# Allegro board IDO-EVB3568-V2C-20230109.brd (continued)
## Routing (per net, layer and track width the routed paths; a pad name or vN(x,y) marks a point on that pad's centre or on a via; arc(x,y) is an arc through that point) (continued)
MIPI_CSI_CLK0P: length 6
  TOP w0.102: J19.18 57.52,9.57 57.65,9.69 57.65,10.02 57.86,10.24 57.86,11 57.73,11.13 D99.9 D99.2 57.73,12.84 57.85,12.96 57.85,13.1 57.75,13.21 57.75,13.71 57.43,14.02 57.43,14.02 R147.2
MIPI_CSI_CLK1N: length 6.5
  TOP w0.102: J20.17 38.96,9.35 38.83,9.48 38.83,10.89 38.24,11.48 37.11,11.48 37.01,11.58 37.01,11.83 D105.1 37.06,12.6 37.06,13.04 R158.2
MIPI_CSI_CLK1P: length 6.5
  TOP w0.102: J20.18 38.46,9.35 38.58,9.47 38.58,10.78 38.13,11.23 37,11.23 36.75,11.48 36.75,11.83 D106.1 36.7,12.6 36.7,13.06 36.42,13.34 R157.2
MIPI_CSI_D0N: length 6
  TOP w0.102: R139.8 61.46,14.19 61.32,14.05 61.32,13.4 61.02,13.1 61.02,12.76 61.15,12.64 D98.1 D98.10 61.15,10.98 61.02,10.86 61.02,9.99 60.9,9.87 60.9,9.69 61.02,9.57 J19.11
MIPI_CSI_D0P: length 6
  TOP w0.102: R139.7 60.91,14.18 61.06,14.02 61.06,13.5 60.77,13.21 60.77,12.76 60.65,12.64 D98.2 D98.9 60.65,11.01 60.77,10.88 60.77,10.1 60.65,9.97 60.65,9.69 60.52,9.57 J19.12
MIPI_CSI_D1N: length 6.1
  TOP w0.102: R139.6 60.3,14.23 60.3,13.93 59.52,13.15 59.52,12.96 59.65,12.84 D98.4 D98.7 59.65,11.01 59.52,10.88 59.52,10.5 59.41,10.39 59.41,9.69 59.52,9.57 J19.14
MIPI_CSI_D1P: length 6.1
  TOP w0.102: J19.15 59.02,9.57 59.16,9.7 59.16,10.49 59.27,10.61 59.27,10.86 59.15,10.98 D98.6 D98.5 59.15,12.84 59.27,12.96 59.27,13.26 59.99,13.98 59.99,14.19 R139.5
MIPI_CSI_D2N: length 6.3
  TOP w0.102: J19.20 56.52,9.41 56.4,9.54 56.4,10.32 56.6,10.52 56.6,10.88 56.73,11.01 D99.7 D99.4 56.73,12.84 56.6,12.96 56.6,13.21 56.35,13.46 55.96,13.46 55.65,13.77 55.65,13.92 55.79,14.06 R140.8
MIPI_CSI_D2N_: length 30.7
  TOP w0.102: v2(52.68,11.81) 52.68,12.2 52.52,12.36 52.52,12.67 52.27,12.92 51.68,12.92 50.95,12.2 50.65,12.2 50.5,12.35 v2(50.5,12.39) ; v1(41.56,12.39) 41.34,12.17 41.34,12.06 41.46,11.94 D104.1 D104.10 41.46,10.47 41.34,10.35 41.34,10.25 41.83,9.76 41.83,9.5 41.96,9.38 J20.11
  BOTTOM w0.102: R141.5 55.74,13.89 55.84,13.79 56.08,13.79 57.52,13.79 58.58,13.79 58.98,13.39 58.98,12.91 58.98,12.7 58.55,12.27 56.23,12.27 55.93,12.57 55.68,12.57 55.37,12.27 54.91,12.27 54.61,12.57 54.36,12.57 54.05,12.27 52.63,12.27 52.5,12.14 52.5,11.91 52.61,11.81 v2(52.68,11.81) ; v1(41.56,12.39) 41.33,12.15 41.33,11.28 41.63,10.97 43.56,10.97 44.47,11.89 49.24,11.89 49.6,12.24 50.32,12.24 50.46,12.39 v2(50.5,12.39)
MIPI_CSI_D2P: length 6.3
  TOP w0.102: J19.21 56.02,9.42 56.15,9.54 56.15,10.43 56.35,10.63 56.35,10.86 56.23,10.98 D99.6 D99.5 56.23,12.84 56.35,12.96 56.35,13.1 56.25,13.21 55.85,13.21 55.39,13.67 55.39,13.85 55.24,14 R140.7
MIPI_CSI_D2P_: length 30.8
  TOP w0.102: v2(50.5,11.81) 50.63,11.94 51.06,11.94 51.78,12.67 52.16,12.67 52.26,12.57 52.26,12.36 52.1,12.2 v2(52.1,11.81) ; v1(40.87,12.39) 41.09,12.17 41.09,12.07 40.96,11.94 D104.2 D104.9 40.96,10.5 41.09,10.38 41.09,10.15 41.58,9.65 41.58,9.45 41.46,9.33 J20.12
  BOTTOM w0.102: v2(52.1,11.81) 52.25,11.95 52.25,12.25 52.52,12.52 53.95,12.52 54.25,12.83 54.71,12.83 55.02,12.52 55.27,12.52 55.57,12.83 56.03,12.83 56.34,12.52 58.44,12.52 58.72,12.81 58.72,13.28 58.47,13.53 57.41,13.53 57.41,13.53 57.04,13.53 57.04,13.53 55.98,13.53 55.66,13.53 55.19,14 R141.6 ; v1(40.87,12.39) 41.07,12.18 41.07,11.17 41.53,10.72 43.66,10.72 44.58,11.63 49.35,11.63 49.7,11.99 50.27,11.99 50.44,11.81 v2(50.5,11.81)
MIPI_CSI_D3N: length 6.1
  TOP w0.102: J19.23 55.02,9.39 54.9,9.51 54.9,10 54.56,10.34 54.56,10.9 D100.1 55.06,11.41 54.56,11.91 54.56,13.72 54.74,13.9 R140.6
MIPI_CSI_D3N_: length 25.4
  TOP w0.102: v1(40.06,12.43) 39.81,12.18 39.81,12.03 39.96,11.88 D104.4 D104.7 39.96,10.5 39.84,10.38 39.84,10.25 40.33,9.76 40.33,9.48 40.46,9.35 J20.14
  BOTTOM w0.102: v1(40.06,12.43) 40.06,12.49 39.86,12.69 39.86,13.17 40.01,13.31 40.18,13.31 40.58,12.92 41.94,12.92 42.14,12.72 42.14,11.76 42.54,11.35 43.31,11.35 43.64,11.68 43.64,12.67 43.87,12.9 44.21,12.9 44.31,12.8 44.31,12.49 44.56,12.24 44.98,12.24 45.23,12.49 45.23,12.8 45.33,12.9 45.53,12.9 45.63,12.8 45.63,12.49 45.88,12.24 46.3,12.24 46.55,12.49 46.55,12.8 46.65,12.9 50.8,12.9 51.16,12.55 51.84,12.55 52.2,12.9 53.87,12.9 54.58,13.62 54.58,13.92 54.69,14.02 R141.7
MIPI_CSI_D3P: length 6.1
  TOP w0.102: J19.24 54.52,9.44 54.65,9.56 54.65,9.89 54.31,10.24 54.31,10.9 D101.1 53.8,11.41 54.31,11.91 54.31,13.79 54.19,13.91 R140.5
MIPI_CSI_D3P_: length 25.4
  TOP w0.102: v1(39.31,12.43) 39.55,12.19 39.55,12.02 39.46,11.93 D104.5 D104.6 39.46,10.47 39.59,10.35 39.59,10.15 40.08,9.65 40.08,9.47 39.96,9.35 J20.15
  BOTTOM w0.102: R141.8 54.14,14.11 54.33,13.92 54.33,13.73 53.76,13.16 52.09,13.16 51.74,12.8 51.26,12.8 50.91,13.16 46.54,13.16 46.29,12.91 46.29,12.6 46.19,12.5 45.99,12.5 45.89,12.6 45.89,12.91 45.64,13.16 45.22,13.16 44.97,12.91 44.97,12.6 44.87,12.5 44.67,12.5 44.57,12.6 44.57,12.91 44.32,13.16 43.76,13.16 43.38,12.78 43.38,11.79 43.21,11.61 42.65,11.61 42.39,11.86 42.39,12.83 42.05,13.17 40.68,13.17 40.29,13.57 39.91,13.57 39.61,13.27 39.61,12.65 39.39,12.43 v1(39.31,12.43)
MIPI_CSI_RX_CLK0N: length 102.5
  TOP w0.102: v1(91.43,33.36) 91.19,33.6 90.67,33.6 90.42,33.85 90.42,34.72 90.88,35.18 90.88,36.88 91.64,37.65 91.64,54.5 89.15,56.99 89.15,58.16 88.03,59.29 86.11,59.29 84.89,58.06 62.79,58.06 60.8,60.06 60.8,60.28 60.67,60.4 J2.103 ; v1(58.31,16.19) 58.31,16.18 58.05,15.92 58.05,15.53 R148.1
  BOTTOM w0.102: v1(58.31,16.19) 58.23,16.19 58.06,16.36 58.06,19.35 58.96,20.24 70.39,20.24 80.29,30.15 81.18,30.15 82.42,31.39 85.69,31.39 87.15,32.85 88.32,32.85 88.95,33.48 89.51,33.48 89.61,33.58 91.21,33.58 v1(91.43,33.36)
MIPI_CSI_RX_CLK0P: length 102.5
  TOP w0.102: v1(91.43,34.05) 91.24,33.86 90.78,33.86 90.68,33.96 90.68,34.62 91.14,35.07 91.14,36.78 91.9,37.54 91.9,54.61 89.41,57.1 89.41,58.27 88.13,59.54 86.01,59.54 84.78,58.32 62.89,58.32 61.05,60.16 61.05,60.28 61.17,60.4 J2.101 ; R147.1 57.79,15.62 57.79,15.92 v1(57.53,16.18)
  BOTTOM w0.102: v1(57.53,16.18) 57.63,16.18 57.81,16.36 57.81,19.46 58.85,20.5 70.28,20.5 80.19,30.4 81.08,30.4 82.32,31.65 85.59,31.65 87.04,33.1 88.21,33.1 88.85,33.73 89.41,33.73 89.51,33.83 91.21,33.83 v1(91.43,34.05)
MIPI_CSI_RX_CLK1N: length 126.1
  TOP w0.102: v2(39.57,15.65) 39.41,15.8 37.9,15.8 37.01,14.91 37.01,14.6 R158.1 ; v2(92.43,34.54) 92.43,34.57 92.28,34.72 92.02,34.72 91.73,35.01 91.73,35.78 92.41,36.45 92.41,54.83 89.84,57.4 89.84,58.5 88.37,59.97 85.73,59.97 84.56,58.8 63.12,58.8 61.8,60.12 61.8,60.55 61.67,60.68 J2.99
  BOTTOM w0.102: v2(39.57,15.65) 39.74,15.81 43.61,15.81 44.26,15.16 51.39,15.16 51.88,15.64 51.88,17.06 52.29,17.47 52.29,18.02 52.56,18.29 53.09,18.29 53.34,18.54 53.34,19.52 56.62,22.8 69.8,22.8 78.24,31.23 78.24,32.01 78.7,32.47 80.24,32.47 81.23,33.46 84.96,33.46 88.14,36.64 90.15,36.64 91.14,35.66 91.14,35.03 91.46,34.71 91.87,34.71 92.29,34.71 92.43,34.57 v2(92.43,34.54)
MIPI_CSI_RX_CLK1P: length 126.1
  TOP w0.102: v2(92.43,35.13) 92.43,35.1 92.3,34.98 92.13,34.98 91.99,35.12 91.99,35.67 92.66,36.35 92.66,54.94 90.09,57.51 90.09,58.6 88.47,60.22 85.62,60.22 84.45,59.06 63.22,59.06 62.05,60.23 62.05,60.56 62.17,60.68 J2.97 ; R157.1 36.75,14.57 36.75,15.02 37.79,16.05 39.44,16.05 v2(39.6,16.23)
  BOTTOM w0.102: v2(92.43,35.13) 92.27,34.96 91.87,34.96 91.56,34.96 91.39,35.14 91.39,35.76 90.26,36.89 88.03,36.89 84.86,33.72 81.13,33.72 80.14,32.73 78.59,32.73 77.98,32.12 77.98,31.34 69.7,23.05 56.51,23.05 53.09,19.62 53.09,18.64 52.98,18.54 52.45,18.54 52.03,18.12 52.03,17.57 51.63,17.17 51.63,15.75 51.29,15.41 44.37,15.41 43.72,16.07 39.76,16.07 v2(39.6,16.23)
MIPI_CSI_RX_D0N: length 100.3
  TOP w0.102: J2.119 56.67,60.4 56.8,60.28 56.8,59.66 61.39,55.07 85.06,55.07 85.75,54.38 87.27,54.38 88.6,53.06 88.6,42.62 88.34,42.37 86.31,42.37 86.06,42.12 86.06,41.47 86.31,41.22 88.37,41.22 88.47,41.12 88.47,40.69 88.37,40.59 86.08,40.59 85.8,40.31 85.8,38.3 86.77,37.34 86.77,34.44 83.85,31.52 83.85,29.29 v1(83.64,29.08) ; R139.1 61.46,15.43 61.29,15.6 61.29,15.77 61.62,16.1 61.62,17.01 v1(61.95,17.35)
  BOTTOM w0.102: v1(61.95,17.35) 61.63,17.67 61.63,17.79 62.34,18.49 62.56,18.49 62.69,18.36 62.69,18.03 62.82,17.9 63.06,17.9 63.2,18.03 63.2,18.36 63.32,18.49 70.84,18.49 81.03,28.68 81.87,28.68 82.73,29.54 83.74,29.54 83.85,29.44 83.85,29.29 v1(83.64,29.08)
MIPI_CSI_RX_D0P: length 100.3
  TOP w0.102: J2.117 57.17,60.4 57.05,60.28 57.05,59.76 61.49,55.32 85.17,55.32 85.85,54.64 87.38,54.64 88.85,53.16 88.85,42.52 88.45,42.11 86.41,42.11 86.31,42.01 86.31,41.58 86.41,41.48 88.47,41.48 88.72,41.23 88.72,40.59 88.47,40.34 86.18,40.34 86.06,40.21 86.06,38.41 87.02,37.44 87.02,34.34 84.1,31.42 84.1,29.31 v1(84.33,29.08) ; R139.2 60.91,15.52 61.04,15.65 61.04,15.88 61.36,16.2 61.36,17.05 v1(61.06,17.35)
  BOTTOM w0.102: v1(84.33,29.08) 84.1,29.31 84.1,29.54 83.85,29.79 82.63,29.79 81.76,28.93 80.92,28.93 70.74,18.75 62.23,18.75 61.38,17.89 61.38,17.67 v1(61.06,17.35)
MIPI_CSI_RX_D1N: length 100.4
  TOP w0.102: J2.115 57.67,60.4 57.8,60.28 57.8,59.73 61.69,55.83 85.44,55.83 86.15,55.12 87.66,55.12 89.36,53.42 89.36,40.08 89.1,39.83 86.94,39.83 86.69,39.57 86.69,38.94 86.94,38.68 88.72,38.68 88.85,38.56 88.85,38.28 88.62,38.05 87.85,38.05 87.5,37.7 87.5,34.01 84.81,31.32 84.81,30.21 v1(84.57,29.98) ; v1(60.43,18.14) 60.21,18.35 60.04,18.35 59.83,18.14 59.83,17.11 60.12,16.81 60.6,16.81 60.68,16.74 60.68,16.43 60.6,16.36 60.38,16.36 60.26,16.24 60.26,15.91 60.41,15.76 R139.3
  BOTTOM w0.102: v1(84.57,29.98) 84.78,30.18 84.78,30.28 84.63,30.43 82.52,30.43 81.53,29.44 80.72,29.44 71.05,19.76 62.56,19.76 61.14,18.34 60.63,18.34 v1(60.43,18.14)
MIPI_CSI_RX_D1P: length 100.5
  TOP w0.102: J2.113 58.17,60.4 58.05,60.28 58.05,59.83 61.8,56.08 85.55,56.08 86.26,55.37 87.76,55.37 89.61,53.52 89.61,39.98 89.21,39.57 87.05,39.57 86.94,39.47 86.94,39.04 87.05,38.94 88.83,38.94 89.1,38.66 89.1,38.17 88.73,37.8 87.96,37.8 87.76,37.59 87.76,33.91 85.06,31.22 85.06,30.21 v1(85.28,29.99) ; R139.4 59.86,15.76 60,15.91 60,16.04 59.58,16.47 59.58,18.25 59.93,18.61 60.21,18.61 v1(60.43,18.82)
  BOTTOM w0.102: v1(85.28,29.99) 85.04,30.24 85.04,30.38 84.73,30.68 82.42,30.68 81.43,29.69 80.62,29.69 70.94,20.02 62.45,20.02 61.03,18.59 60.66,18.59 v1(60.43,18.82)
MIPI_CSI_RX_D2N: length 101.4
  TOP w0.102: v1(88.9,34.22) 88.68,34.45 88.49,34.45 88.24,34.7 88.24,36.6 90.12,38.48 90.12,53.8 88.06,55.85 86.56,55.85 85.85,56.57 62.08,56.57 58.8,59.85 58.8,60.28 58.67,60.4 J2.111 ; R140.1 55.78,15.17 55.78,15.64 56.06,15.92 56.06,16.13 v1(56.14,16.21)
  BOTTOM w0.102: R141.4 55.6,15.32 55.6,15.67 v1(56.14,16.21) 56.14,16.29 55.93,16.49 55.93,18.48 56.16,18.71 56.16,19.73 57.71,21.29 70.41,21.29 80.06,30.94 80.88,30.94 81.89,31.95 85.57,31.95 88.06,34.44 88.68,34.44 v1(88.9,34.22)
MIPI_CSI_RX_D2P: length 101.4
  TOP w0.102: R140.2 55.32,15.24 55.32,15.54 55.63,15.86 55.63,16.04 55.48,16.2 v1(55.46,16.2) ; J2.109 59.17,60.4 59.05,60.28 59.05,59.95 62.18,56.82 85.95,56.82 86.66,56.11 88.17,56.11 90.37,53.9 90.37,38.38 88.49,36.5 88.49,34.8 88.6,34.7 88.69,34.7 v1(88.9,34.92)
  BOTTOM w0.102: R141.3 55.19,15.29 55.35,15.44 55.35,15.77 55.48,15.91 55.48,16.18 v1(55.46,16.2) 55.68,16.41 55.68,17.16 55.6,17.23 55.6,17.69 55.68,17.77 55.68,18.59 55.9,18.81 55.9,19.83 57.61,21.54 70.31,21.54 79.96,31.19 80.77,31.19 81.79,32.21 85.47,32.21 87.96,34.7 88.68,34.7 v1(88.9,34.92)
MIPI_CSI_RX_D3N: length 105.1
  TOP w0.102: R140.3 54.74,15.31 54.61,15.44 54.61,15.65 54.5,15.76 54.5,15.99 54.71,16.2 v1(54.72,16.2) ; J2.107 59.67,60.4 59.8,60.28 59.8,59.99 62.48,57.3 85.24,57.3 86.54,58.6 87.7,58.6 88.47,57.83 88.47,56.57 90.88,54.15 90.88,38.18 89.1,36.4 89.1,35.64 89.35,35.39 89.59,35.39 v1(89.81,35.16)
  BOTTOM w0.102: v1(89.81,35.16) 89.59,35.38 87.94,35.38 85.27,32.72 81.59,32.72 80.57,31.7 79.76,31.7 70.08,22.02 56.95,22.02 54.23,19.31 54.23,18.81 54.41,18.64 54.41,17.5 54.56,17.34 54.56,17.09 54.41,16.94 54.41,16.51 v1(54.72,16.2) 54.72,16.18 54.56,16.02 54.56,15.4 54.69,15.27 R141.2
MIPI_CSI_RX_D3P: length 105.2
  TOP w0.102: J2.105 60.17,60.4 60.05,60.28 60.05,60.1 62.59,57.56 85.14,57.56 86.43,58.85 87.81,58.85 88.72,57.94 88.72,56.67 91.14,54.26 91.14,38.07 89.36,36.29 89.36,35.75 89.46,35.64 89.6,35.64 v1(89.81,35.86) ; R140.4 54.36,15.32 54.36,15.54 53.92,15.97 53.92,16.13 v1(53.87,16.18)
  BOTTOM w0.102: v1(89.81,35.86) 89.59,35.64 87.83,35.64 85.17,32.97 81.48,32.97 80.47,31.95 79.65,31.95 69.98,22.28 57.05,22.28 56.84,22.28 53.98,19.41 53.98,18.71 54.15,18.53 54.15,16.46 v1(53.87,16.18) 54.31,15.75 54.31,15.35 R141.1
MIPI_DSI_TX0_CLKN: length 61.8
  TOP w0.102: v1(28.12,36.55) 27.89,36.32 26.29,36.32 26.11,36.5 26.11,36.89 25.77,37.24 25.38,37.24 24.55,38.06 23.58,38.06 23.46,38.18 D51.2 D51.9 21.98,38.18 21.88,38.08 21.74,38.08 21.47,38.35 21.41,38.35 21.29,38.48 21.29,38.56 21.17,38.68 21.02,38.68 20.9,38.56 20.9,38.43 20.83,38.35 20.61,38.35 v1(20.39,38.58) ; J2.133 53.17,60.59 53.3,60.47 53.3,59.62 52.98,59.31 52.98,58.85 53.3,58.54 53.3,58.3 52.98,57.99 52.98,57.53 53.3,57.22 53.3,56.22 53.16,56.08 53.16,55.8 v2(53.02,55.65)
  BOTTOM w0.102: v1(28.12,36.55) 28.37,36.3 28.93,36.3 29.08,36.14 29.36,36.14 29.54,35.97 29.54,35.81 29.69,35.66 30.3,35.66 30.61,35.36 30.86,35.36 31.16,35.66 31.62,35.66 31.93,35.36 32.18,35.36 32.48,35.66 32.94,35.66 33.25,35.36 33.5,35.36 33.8,35.66 34.16,35.66 34.58,36.08 34.58,37 36.25,38.66 36.25,39.27 35.79,39.73 35.79,40.44 36.25,40.89 36.25,42.67 37.72,44.15 37.72,49.4 40.16,51.84 44.48,51.84 45.44,50.88 46.2,50.88 47.32,51.99 48.97,51.99 49.78,52.81 49.78,53.67 50.26,54.15 52.25,54.15 53.19,55.09 53.19,55.48 v2(53.02,55.65) ; v1(20.39,38.58) 20.19,38.38 19.43,38.38 19.31,38.51 J15.27 18.13,38.51 18.01,38.38 17.72,38.38 R127.1
MIPI_DSI_TX0_CLKP: length 61.8
  TOP w0.102: v1(28.12,35.76) 27.81,36.07 26.19,36.07 25.86,36.4 25.86,36.79 25.66,36.98 25.27,36.98 24.45,37.81 23.61,37.81 23.49,37.68 D51.1 D51.10 22.01,37.68 21.86,37.83 21.63,37.83 21.36,38.1 20.6,38.1 v1(20.39,37.88) ; J2.131 53.67,60.61 53.55,60.48 53.55,59.51 53.24,59.2 53.24,58.96 53.55,58.65 53.55,58.19 53.24,57.88 53.24,57.64 53.55,57.33 53.55,56.11 53.42,55.98 53.42,55.83 v2(53.59,55.65)
  BOTTOM w0.102: v2(53.59,55.65) 53.44,55.5 53.44,54.99 52.35,53.9 50.37,53.9 50.04,53.57 50.04,52.7 49.08,51.74 47.42,51.74 46.3,50.62 45.34,50.62 44.37,51.59 40.26,51.59 37.97,49.3 37.97,44.04 36.5,42.57 36.5,40.79 36.04,40.33 36.04,39.83 36.5,39.37 36.5,38.56 34.84,36.89 34.84,35.98 34.27,35.41 33.91,35.41 33.6,35.1 33.14,35.1 32.84,35.41 32.59,35.41 32.28,35.1 31.82,35.1 31.52,35.41 31.27,35.41 30.96,35.1 30.5,35.1 30.2,35.41 29.46,35.41 28.83,36.04 28.4,36.04 v1(28.12,35.76) ; v1(20.39,37.88) 20.14,38.13 19.46,38.13 19.34,38.01 J15.26 18.1,38.01 18.05,38.06 17.68,38.06 R126.1
MIPI_DSI_TX0_D0N: length 62
  TOP w0.102: J2.141 51.17,60.64 51.3,60.51 51.3,60.31 51.74,59.87 51.74,58.47 49.23,55.96 49.23,54.36 49.13,54.27 48.93,54.27 48.8,54.4 v2(48.79,54.4) ; v1(20.41,41.6) 20.63,41.38 21.74,41.38 21.9,41.22 22.05,41.22 22.2,41.38 D53.1 22.32,41.96 22.93,41.35 23.7,41.35 24.21,40.84 25.91,40.84 26.8,39.95 28.2,39.95 28.64,39.51 v1(28.94,39.51)
  BOTTOM w0.102: R122.1 17.63,41.17 17.78,41.17 18.11,41.51 J15.33 19.35,41.51 19.46,41.4 20.21,41.4 v1(20.41,41.6) ; v1(28.94,39.51) 28.94,39.11 29.06,38.99 29.06,37.9 29.36,37.59 29.82,37.59 30.4,37.01 32.77,37.01 34.06,38.3 34.06,39.47 33.81,39.73 33.81,40.72 34.39,41.3 34.39,43.99 36.42,46.02 36.42,50.24 40.64,54.46 41.53,54.46 41.78,54.21 41.78,53.9 41.89,53.8 42.09,53.8 42.19,53.9 42.19,54.21 42.44,54.46 42.85,54.46 43.11,54.21 43.11,53.9 43.21,53.8 43.41,53.8 43.51,53.9 43.51,54.21 43.76,54.46 44.18,54.46 44.43,54.21 44.43,53.9 44.53,53.8 44.73,53.8 44.83,53.9 44.83,54.21 45.08,54.46 45.5,54.46 45.75,54.21 45.75,53.9 45.85,53.8 46.05,53.8 46.15,53.9 46.15,54.21 46.4,54.46 46.82,54.46 47.07,54.21 47.07,53.9 47.17,53.8 47.37,53.8 47.47,53.9 47.47,54.21 47.72,54.46 48.21,54.46 48.44,54.23 48.62,54.23 v2(48.79,54.4)
MIPI_DSI_TX0_D0P: length 61.8
  TOP w0.102: v2(48.82,53.82) 48.89,53.82 49.08,54.01 49.24,54.01 49.48,54.25 49.48,55.85 51.99,58.37 51.99,59.97 51.55,60.42 51.55,60.52 51.67,60.64 J2.139 ; v1(20.41,40.91) 20.63,41.13 21.64,41.13 D52.1 22.32,40.56 22.85,41.1 23.59,41.1 24.1,40.59 25.8,40.59 26.69,39.7 28.09,39.7 28.47,39.32 v1(28.47,39.01)
  BOTTOM w0.102: v1(28.47,39.01) 28.67,39.01 28.8,38.88 28.8,37.79 29.26,37.34 29.71,37.34 30.3,36.75 32.87,36.75 34.32,38.2 34.32,39.58 34.06,39.83 34.06,40.61 34.65,41.2 34.65,43.89 36.68,45.92 36.68,50.14 40.75,54.2 41.43,54.2 41.53,54.1 41.53,53.79 41.78,53.54 42.19,53.54 42.44,53.79 42.44,54.1 42.55,54.2 42.75,54.2 42.85,54.1 42.85,53.79 43.1,53.54 43.52,53.54 43.77,53.79 43.77,54.1 43.87,54.2 44.07,54.2 44.17,54.1 44.17,53.79 44.42,53.54 44.84,53.54 45.09,53.79 45.09,54.1 45.19,54.2 45.39,54.2 45.49,54.1 45.49,53.79 45.74,53.54 46.16,53.54 46.41,53.79 46.41,54.1 46.51,54.2 46.71,54.2 46.81,54.1 46.81,53.79 47.06,53.54 47.48,53.54 47.73,53.79 47.73,54.1 47.83,54.2 48.11,54.2 48.34,53.98 48.67,53.98 v2(48.82,53.82) ; v1(20.41,40.91) 20.18,41.14 19.43,41.14 19.29,41.01 J15.32 17.99,41.01 17.75,40.76 R122.2
MIPI_DSI_TX0_D1N: length 61.2
  TOP w0.102: v1(20.36,40.15) 20.61,39.9 21.08,39.9 21.41,39.57 21.84,39.57 21.95,39.68 D51.6 D51.5 23.63,39.68 23.76,39.56 25.23,39.56 26.49,38.3 26.75,38.3 26.87,38.43 26.87,38.56 26.99,38.68 27.26,38.68 27.38,38.56 27.38,38.43 27.51,38.3 27.56,38.3 27.84,38.02 v1(28.17,38.02) ; J2.137 52.17,60.53 52.3,60.4 52.3,57.94 52.06,57.7 52.06,57.26 52.3,57.03 52.3,56.77 52.18,56.65 51.7,56.65 51.49,56.87 50.98,56.87 49.78,55.68 49.78,53.42 49.35,52.98 49.1,52.98 v2(48.92,53.16)
  BOTTOM w0.102: v1(20.36,40.15) 20.09,39.88 19.45,39.88 19.33,40.01 J15.30 18.01,40.01 17.89,40.13 17.73,40.13 17.6,40.26 R122.3 ; v1(28.17,38.02) 28.15,37.72 28.81,37.06 29.36,37.06 29.95,36.47 33.78,36.47 33.96,36.66 33.96,37.39 35.03,38.46 35.03,41.76 35.43,42.17 35.43,42.62 35.15,42.9 35.15,43.38 35.43,43.66 35.43,44.02 37.01,45.6 37.01,49.66 40.05,52.7 41.24,52.7 41.34,52.81 41.34,52.94 41.59,53.19 42,53.19 42.25,52.94 42.25,52.81 42.36,52.7 42.56,52.7 42.66,52.81 42.66,52.94 42.91,53.19 43.32,53.19 43.57,52.94 43.57,52.81 43.68,52.7 43.88,52.7 43.98,52.81 43.98,52.94 44.23,53.19 44.65,53.19 44.9,52.94 44.9,52.81 45,52.7 45.2,52.7 45.3,52.81 45.3,52.94 45.55,53.19 45.97,53.19 46.22,52.94 46.22,52.81 46.32,52.7 46.52,52.7 46.62,52.81 46.62,52.94 46.87,53.19 47.29,53.19 47.54,52.94 47.54,52.81 47.64,52.7 48.18,52.7 48.46,52.98 48.75,52.98 48.89,53.13 48.89,53.13 v2(48.92,53.16)
MIPI_DSI_TX0_D1P: length 61.1
  TOP w0.102: v2(48.91,52.58) 49.06,52.73 49.46,52.73 50.04,53.31 50.04,55.57 51.08,56.62 51.38,56.62 51.6,56.4 52.28,56.4 52.55,56.66 52.55,57.13 52.31,57.37 52.31,57.59 52.55,57.83 52.55,60.47 52.67,60.6 J2.135 ; v1(27.64,37.57) 27.64,37.87 27.45,38.05 26.39,38.05 25.13,39.31 23.76,39.31 23.63,39.18 D51.4 D51.7 21.98,39.18 21.84,39.32 21.31,39.32 20.98,39.65 20.58,39.65 v1(20.36,39.43)
  BOTTOM w0.102: v2(48.91,52.58) 48.77,52.73 48.57,52.73 48.29,52.45 47.53,52.45 47.28,52.7 47.28,52.83 47.18,52.93 46.98,52.93 46.88,52.83 46.88,52.7 46.63,52.45 46.21,52.45 45.96,52.7 45.96,52.83 45.86,52.93 45.66,52.93 45.56,52.83 45.56,52.7 45.31,52.45 44.89,52.45 44.64,52.7 44.64,52.83 44.54,52.93 44.34,52.93 44.24,52.83 44.24,52.7 43.98,52.45 43.57,52.45 43.32,52.7 43.32,52.83 43.22,52.93 43.02,52.93 42.91,52.83 42.91,52.7 42.66,52.45 42.25,52.45 42,52.7 42,52.83 41.9,52.93 41.7,52.93 41.59,52.83 41.59,52.7 41.34,52.45 40.16,52.45 37.26,49.56 37.26,45.49 35.69,43.92 35.69,43.56 35.41,43.28 35.41,43 35.69,42.72 35.69,42.06 35.28,41.66 35.28,38.35 34.21,37.29 34.21,36.55 33.88,36.22 29.84,36.22 29.26,36.8 28.7,36.8 27.97,37.54 v1(27.64,37.57) ; v1(20.36,39.43) 20.17,39.63 19.44,39.63 19.31,39.51 J15.29 18.16,39.51 17.79,39.87 17.65,39.87 R122.4
MIPI_DSI_TX0_D2N: length 61.8
  TOP w0.102: v1(20.4,37.11) 20.61,36.89 20.83,36.89 20.9,36.97 20.9,37.16 21.02,37.28 21.17,37.28 21.29,37.16 21.29,37.02 21.41,36.89 21.61,36.89 21.73,37.02 D49.6 D49.5 23.41,37.02 23.53,36.89 24.6,36.89 26.75,34.75 27.84,34.75 v1(28.07,34.98) ; J2.129 54.17,60.61 54.28,60.5 54.28,59.66 54.1,59.48 54.1,58.96 54.28,58.79 54.28,58.34 54.1,58.16 54.1,57.64 54.28,57.47 54.28,55.39 v2(54.06,55.17)
  BOTTOM w0.102: v1(28.07,34.98) 28.3,34.75 34.72,34.75 35.18,35.2 35.18,36.63 36.96,38.41 36.96,42.34 38.4,43.79 38.4,49 40.59,51.18 44.25,51.18 45.19,50.24 46.83,50.24 47.72,51.13 49.02,51.13 51.46,53.57 53.26,53.57 53.37,53.67 53.37,53.92 53.7,54.25 54.1,54.25 54.23,54.38 54.23,55 v2(54.06,55.17) ; v1(20.4,37.11) 20.17,36.88 19.63,36.88 19.5,37.01 J15.24 18.16,37.01 17.99,36.84 17.99,36.84 17.75,36.6 17.61,36.6 R123.1
MIPI_DSI_TX0_D2P: length 61.6
  TOP w0.102: v2(54.74,55.19) 54.53,55.4 54.53,57.57 54.36,57.75 54.36,58.05 54.53,58.23 54.53,58.89 54.36,59.07 54.36,59.37 54.53,59.55 54.53,60.53 54.67,60.67 J2.127 ; v1(20.4,36.43) 20.61,36.64 21.61,36.64 21.73,36.52 D49.7 D49.4 23.46,36.52 23.58,36.64 24.49,36.64 26.64,34.49 27.86,34.49 v1(28.07,34.28)
  BOTTOM w0.102: v1(20.4,36.43) 20.2,36.63 19.63,36.63 19.5,36.51 J15.23 18.12,36.51 17.93,36.32 17.68,36.32 17.57,36.22 R123.2 ; v2(54.74,55.19) 54.48,54.94 54.48,54.28 54.21,54 53.8,54 53.62,53.82 53.62,53.56 53.37,53.31 51.57,53.31 49.13,50.88 47.83,50.88 46.94,49.99 45.08,49.99 44.14,50.93 40.69,50.93 38.66,48.89 38.66,43.68 37.21,42.24 37.21,38.3 35.43,36.53 35.43,35.1 34.83,34.49 28.28,34.49 v1(28.07,34.28)
MIPI_DSI_TX0_D3N: length 63.9
  TOP w0.102: v2(55.24,55.65) 55.5,55.91 55.5,56.13 55.02,56.61 55.02,60.18 55.27,60.43 55.27,60.58 55.17,60.68 J2.125 ; v1(20.37,35.64) 20.6,35.41 20.93,35.41 21.03,35.51 21.03,35.64 21.15,35.75 21.29,35.75 21.41,35.64 21.41,35.53 21.54,35.41 21.79,35.41 21.9,35.52 D49.9 D49.2 23.39,35.52 23.49,35.41 23.91,35.41 26.22,33.1 27.48,33.1 v1(27.73,33.35)
  BOTTOM w0.102: v2(55.24,55.65) 55.47,55.42 55.47,54.39 54.02,52.93 51.82,52.93 48.49,49.61 44.91,49.61 43.87,50.65 41.1,50.65 39.17,48.72 39.17,43.69 37.62,42.14 37.62,38.13 35.79,36.3 35.79,34.09 35.23,33.53 28.47,33.53 28.07,33.13 27.95,33.13 v1(27.73,33.35) ; v1(20.37,35.64) 20.14,35.41 19.48,35.41 19.38,35.51 J15.21 18.18,35.51 18.11,35.43 17.99,35.43 17.81,35.61 17.55,35.61 R123.3
MIPI_DSI_TX0_D3P: length 64
  TOP w0.102: J2.123 55.67,60.65 55.52,60.5 55.52,60.33 55.27,60.07 55.27,56.72 55.75,56.24 55.75,55.88 v2(56.01,55.63) ; v1(20.37,34.95) 20.57,35.15 21.77,35.15 21.9,35.02 D49.10 D49.1 23.43,35.02 23.57,35.15 23.8,35.15 26.11,32.84 27.54,32.84 v1(27.73,32.66)
  BOTTOM w0.102: v2(56.01,55.63) 55.73,55.35 55.73,54.28 54.13,52.68 51.92,52.68 48.59,49.35 44.8,49.35 43.76,50.39 41.2,50.39 39.42,48.61 39.42,43.59 37.87,42.04 37.87,38.02 36.04,36.2 36.04,33.99 35.33,33.27 28.58,33.27 28.18,32.88 27.95,32.88 v1(27.73,32.66) ; R123.4 17.6,35.32 17.74,35.32 18.06,35.01 J15.20 19.38,35.01 19.53,35.15 20.17,35.15 v1(20.37,34.95)
MIPI_DSI_TX0_RST: length 9.6
  TOP w0.127: v1(19.84,42.65) 21.92,42.65 22.56,43.28 C90.2 R417.2 24.13,44.33 24.13,46.51 R121.2
  BOTTOM w0.127: v1(19.84,42.65) 19.48,43.01 J15.36
MIPI_DSI_TX0_RST_GPIO4_C3: length 43.9
  TOP w0.127: v1(51.51,55.19) 52.42,54.28 J2.136 ; v1(31.83,55.7) 31.95,55.58 38.79,55.58 v1(39.07,55.3) ; v1(25.91,51.82) 25.77,51.82 22.61,48.65 22.59,48.65 22.57,48.63 21.64,48.63 21.51,48.5 21.51,47.78 23.49,45.8 R417.1
  BOTTOM w0.127: v1(39.07,55.3) 39.22,55.14 50.16,55.14 50.6,54.71 51.03,54.71 v1(51.51,55.19) ; v1(25.91,51.82) 25.91,52.55 26.57,53.21 26.57,55.91 27.89,57.23 30.05,57.23 31.57,55.7 v1(31.83,55.7)
MIPI_DSI_TX1_CLKN: length 52.9
  TOP w0.102: J2.96 62.42,52.41 62.55,52.29 62.55,51.83 66.29,48.08 67.77,48.08 71.98,43.87 71.98,24.41 79.2,17.19 79.2,12.65 79.06,12.51 D37.2 D37.9 79.06,11.01 79.2,10.87 79.2,10.64 80.15,9.68 80.15,9.54 80.04,9.43 J13.27
MIPI_DSI_TX1_CLKP: length 52.8
  TOP w0.102: J13.26 80.54,9.4 80.41,9.54 80.41,9.79 79.45,10.74 79.45,10.87 79.56,10.98 D37.10 D37.1 79.56,12.56 79.45,12.67 79.45,17.3 72.24,24.51 72.24,43.97 67.87,48.34 66.4,48.34 62.8,51.94 62.8,52.26 62.92,52.38 J2.94
MIPI_DSI_TX1_D0N: length 52.7
  TOP w0.102: J13.33 77.04,9.47 77.16,9.6 77.16,9.88 76.78,10.26 76.78,13.57 D38.1 76.78,14.58 76.78,17.37 70.51,23.64 70.51,43.18 67.13,46.56 65.68,46.56 60.55,51.7 60.55,52.08 60.42,52.2 J2.104
MIPI_DSI_TX1_D0P: length 52.7
  TOP w0.102: J2.102 60.92,52.2 60.8,52.08 60.8,51.8 65.79,46.81 67.24,46.81 70.76,43.29 70.76,23.75 77.04,17.48 77.04,14.58 D36.1 77.04,13.57 77.04,10.36 77.42,9.99 77.42,9.61 77.54,9.48 J13.32
MIPI_DSI_TX1_D1N: length 53.2
  TOP w0.102: J13.30 78.54,9.45 78.66,9.57 78.66,9.78 78.25,10.19 77.94,10.19 77.69,10.44 77.69,10.73 77.56,10.86 D37.6 D37.5 77.56,12.54 77.68,12.66 77.68,13.14 78.18,13.64 78.18,17.12 71.25,24.05 71.25,43.51 67.43,47.32 65.99,47.32 61.55,51.76 61.55,52.08 61.42,52.2 J2.100
MIPI_DSI_TX1_D1P: length 53.2
  TOP w0.102: J2.98 61.92,52.2 61.8,52.08 61.8,51.87 66.09,47.57 67.54,47.57 71.5,43.61 71.5,24.16 78.44,17.22 78.44,13.54 77.94,13.04 77.94,12.64 78.06,12.51 D37.4 D37.7 78.06,10.88 77.94,10.76 77.94,10.54 78.04,10.44 78.36,10.44 78.92,9.88 78.92,9.55 79.04,9.43 J13.29
MIPI_DSI_TX1_D2N: length 53.3
  TOP w0.102: J2.92 63.42,52.43 63.55,52.3 63.55,51.9 66.6,48.84 68.07,48.84 72.72,44.2 72.72,24.74 80.35,17.1 80.35,12.66 80.23,12.54 D35.5 D35.6 80.23,10.98 80.34,10.87 80.34,10.64 80.74,10.24 81.2,10.24 81.66,9.78 81.66,9.53 81.54,9.4 J13.24
MIPI_DSI_TX1_D2P: length 53.3
  TOP w0.102: J2.90 63.92,52.49 63.8,52.37 63.8,52 66.7,49.1 68.18,49.1 72.97,44.3 72.97,24.84 80.61,17.21 80.61,12.64 80.73,12.51 D35.4 D35.7 80.73,11.01 80.59,10.87 80.59,10.74 80.85,10.49 81.31,10.49 81.92,9.88 81.92,9.55 82.04,9.43 J13.23
MIPI_DSI_TX1_D3N: length 53.6
  TOP w0.102: J13.21 83.04,9.38 83.16,9.5 83.16,9.85 82.65,10.36 82.14,10.36 81.87,10.63 81.87,10.86 81.73,11.01 D35.9 D35.2 81.73,12.71 81.85,12.83 81.85,13.04 81.36,13.54 81.36,17.22 73.48,25.1 73.48,44.5 68.38,49.61 66.9,49.61 64.55,51.96 64.55,52.32 64.42,52.44 J2.88
MIPI_DSI_TX1_D3P: length 53.6
  TOP w0.102: J13.20 83.54,9.32 83.42,9.45 83.42,9.96 82.75,10.62 82.25,10.62 82.13,10.74 82.13,10.88 82.23,10.98 D35.10 D35.1 82.23,12.71 82.11,12.83 82.11,13.15 81.61,13.64 81.61,17.33 73.74,25.2 73.74,44.61 68.48,49.86 67,49.86 64.8,52.06 64.8,52.35 64.92,52.48 J2.86
MIPI_DSI_TX1_RST: length 8
  TOP w0.127: J13.36 75.54,11.99 74.23,13.3 C80.2 75.13,14.84 R98.2 R418.2
MIPI_TX0_BL_PWM13: length 64.5
  TOP w0.127: U14.2 29.29,13.79 30.43,12.65 32.43,12.65 R138.1 v1(33.85,12.7) ; U13.4 31.33,20.98 R118.2 31.94,21.51 32.4,21.98 34.47,21.98 v1(34.75,22.26) 34.76,22.28 35.79,22.28 36.42,22.91 38.68,22.91 39.47,23.7 40.39,23.7 42.02,22.06 43.15,22.06 43.38,22.3 46.69,22.3 47.96,23.57 47.96,25.12 50.72,27.89 51.26,27.89 51.51,28.14 51.51,30.05 50.7,30.86 50.7,36.7 49.5,37.9 49.5,39.6 51.08,41.17 51.08,42.93 50.54,43.47 50.54,47.05 50.22,47.37 R110.2
  BOTTOM w0.127: v1(34.75,22.26) 34.95,22.06 34.95,16.61 34.11,15.77 34.11,14.38 33.43,13.69 33.43,13.12 v1(33.85,12.7)
MIPI_TX1_BL_PWM12: length 2.6
  TOP w0.127: U12.4 83.83,24.65 83.13,23.95 R100.2 R91.2
MIPI_TX1_BL_PWM12_M0: length 38.3
  TOP w0.127: R91.1 81.64,24.97 80.37,23.7 79.83,23.7 78.61,24.92 78.61,27.18 80.34,28.91 80.34,34.75 80.21,34.87 80.21,39.7 76.4,43.51 76.4,44.91 69.39,51.92 69.14,51.92 68.92,52.13 J2.70
MIPI_TX1_RST_GPIO2_D6: length 61.1
  TOP w0.127: J2.75 67.67,59.86 67.97,59.56 v1(76.53,59.56) ; v1(69.71,37.1) 69.71,34.59 69.74,34.56 69.74,32.74 69.26,32.26 69.26,23.93 69.67,23.52 69.67,22.68 70.05,22.3 70.37,22.3 71.64,21.03 71.64,18.48 72.19,17.93 74.24,17.93 74.63,17.55 74.63,16.23 74.27,15.88 R418.1
  BOTTOM w0.127: v1(69.71,37.1) 70.18,37.57 70.18,38.23 72.47,40.51 72.47,49.61 74.37,51.51 74.37,52.53 74.88,53.04 74.88,57.91 v1(76.53,59.56)
NTC_SARADC_VIN3: length 72.6
  TOP w0.127: J2.5 85.17,62.41 85.3,62.53 85.55,62.53 85.83,62.81 87.25,62.81 91.06,59 91.06,58.04 93.8,55.3 95.53,55.3 97.76,57.53 108.9,57.53 110.16,56.27 110.16,55.66 111.46,54.36 111.46,50.63 118.69,43.39 118.69,42.37 120.09,40.97 120.09,36.65 119.25,35.81 119.25,32.54 120.6,31.19 122.76,31.19 123.52,30.43 124.61,30.43 124.85,30.2 124.94,30.2 126.49,28.65 126.49,28.39 126.67,28.22 126.67,25.22 126.79,25.09 R312.2
PCIE20_CLKREQN_3V3_L: length 2.4
  TOP w0.127: v1(49.46,23.75) 49.52,23.7 R348.2
  BOTTOM w0.127: J27.52 v1(49.46,23.75)
PCIE20_CLKREQN_M2_3V3_L: length 58.5
  TOP w0.127: R348.1 51.49,23.7 v1(51.56,23.77) ; v1(84.99,35.89) 85.04,35.94 85.04,37.16 84.53,37.67 84.53,41.86 83.71,42.68 83.71,49.29 85.92,51.51 J2.2
  BOTTOM w0.127: v1(84.99,35.89) 84.96,35.86 78.54,35.86 73.05,30.38 73.05,29.46 68.69,25.1 55.27,25.1 55.27,25.1 54.69,25.1 53.85,25.1 53.85,25.1 53.54,25.1 52.22,23.77 v1(51.56,23.77)
PCIE20_PERSTN_3V3_L: length 2.6
  TOP w0.127: R347.2 49.81,24.84 v1(49.45,24.48)
  BOTTOM w0.127: J27.50 49.23,24.25 v1(49.45,24.48)
PCIE20_PERSTN_M2_3V3_L: length 56.7
  TOP w0.127: R347.1 v1(51.64,24.84) ; J2.6 84.92,52.28 84.49,51.85 84.49,51.35 82.95,49.8 82.95,42.3 83.77,41.48 83.77,36.93 v1(84.02,36.68)
  BOTTOM w0.127: v1(51.64,24.84) 52.4,25.6 53.64,25.6 53.64,25.6 54.9,25.6 55.48,25.6 55.48,25.6 68.48,25.6 72.5,29.63 72.5,30.59 79.02,37.11 83.59,37.11 v1(84.02,36.68)
PCIE20_PRSNT_3V3_L: length 2.5
  TOP w0.127: v1(39.96,19.5) 38.73,19.5 R382.1
  BOTTOM w0.127: J27.69 v1(39.96,19.5)
PCIE20_PRSNT_3V3_L_GPIO3_A6: length 111.7
  TOP w0.127: v1(51.51,25.81) 50.08,25.81 48.97,24.7 48.97,23.06 47.19,21.29 43.89,21.29 43.56,20.96 39.93,20.96 39.5,21.39 38.31,21.39 37.67,20.74 37.67,19.63 37.8,19.51 R382.2 ; v1(73.46,63.04) 73.23,62.81 72.72,62.81 72.17,62.27 J2.57 ; v1(86.26,36.32) 86.26,37.08 85.29,38.05 85.29,42.24 84.53,43 84.53,48.97 87.35,51.79 v1(88.01,51.79)
  BOTTOM w0.127: v1(73.46,63.04) 73.89,63.47 74.02,63.47 74.35,63.8 75.23,63.8 75.41,63.98 78.49,63.98 78.74,64.24 81.92,64.24 82.68,63.47 82.68,62.53 83.52,61.7 91.67,61.7 92.34,61.03 92.34,59.22 88.7,55.58 88.7,53.9 87.58,52.78 87.58,52.22 v1(88.01,51.79) ; v1(86.26,36.32) 85.6,36.32 84.51,37.41 78.94,37.41 68.15,26.62 52.32,26.62 v1(51.51,25.81)
PCIE20_REFCLKN: length 38.5
  TOP w0.102: R360.1 45.87,23.67 45.97,23.57 46.43,23.57 47.19,24.33 47.19,26.09 48.23,27.13 48.23,45.72 45.67,48.28 45.67,50.29 44.91,51.05 44.14,51.82 38.96,51.82 38.58,52.2 38.58,52.37 38.42,52.53 J2.184
PCIE20_REFCLKN_: length 4.3
  TOP w0.102: v1(42.93,23.6) 43.16,23.37 43.71,23.37 44.04,23.7 44.58,23.7 R360.2
  BOTTOM w0.102: J27.53 42.2,23.5 42.32,23.38 42.71,23.38 v1(42.93,23.6)
PCIE20_REFCLKP: length 38.6
  TOP w0.102: R361.1 46.12,23.32 46.54,23.32 47.45,24.23 47.45,25.98 48.49,27.03 48.49,45.82 45.92,48.39 45.92,50.39 44.25,52.07 39.07,52.07 38.84,52.3 38.84,52.41 38.92,52.5 J2.182
PCIE20_REFCLKP_: length 4.3
  TOP w0.102: R361.2 44.58,23.44 44.15,23.44 43.81,23.11 43.13,23.11 v1(42.93,22.91)
  BOTTOM w0.102: J27.55 42.2,23 42.32,23.13 42.71,23.13 v1(42.93,22.91)
PCIE20_RXN: length 36.3
  TOP w0.102: J2.188 37.42,52.53 37.55,52.4 37.55,52.16 38.63,51.08 43.81,51.08 44.91,49.99 44.91,47.9 47.5,45.31 47.5,27.46 46.43,26.4 46.43,25.7 46.33,25.6 45.97,25.6 45.87,25.7 R355.1
PCIE20_RXN_: length 4.5
  TOP w0.102: R355.2 44.58,25.73 44.09,25.73 v1(43.89,25.93)
  BOTTOM w0.102: v1(43.89,25.93) 43.67,25.71 43.55,25.71 42.78,26.48 42.2,26.48 42.08,26.37 41.99,26.37 41.85,26.5 J27.41
PCIE20_RXP: length 36.3
  TOP w0.102: R356.1 46.12,25.35 46.43,25.35 46.69,25.6 46.69,26.29 47.75,27.36 47.75,45.42 45.16,48.01 45.16,50.09 43.92,51.33 38.74,51.33 37.8,52.27 37.8,52.4 37.92,52.52 J2.186
PCIE20_RXP_: length 4.5
  TOP w0.102: v1(43.9,25.23) 44.15,25.48 44.58,25.48 R356.2
  BOTTOM w0.102: J27.43 41.88,26 41.99,26.11 42.19,26.11 42.31,26.23 42.68,26.23 43.45,25.46 43.67,25.46 v1(43.9,25.23)
PCIE20_TX_N: length 1.3
  TOP w0.102: C212.2 44.58,27.76 44.34,27.76 R357.1
PCIE20_TX_P: length 1.3
  TOP w0.102: C213.2 44.58,27.51 44.34,27.51 R358.1
PCIE20_TXN: length 34.1
  TOP w0.102: J2.192 36.42,52.48 36.58,52.32 36.58,52.09 38.32,50.34 43.43,50.34 44.15,49.63 44.15,47.52 46.76,44.9 46.76,27.94 46.45,27.64 45.97,27.64 45.87,27.74 C212.1
PCIE20_TXN_: length 6.2
  TOP w0.102: v1(42.49,25.08) 42.69,24.87 42.9,24.87 43,24.97 43,25.91 42.14,26.77 42.14,27.51 42.39,27.76 42.68,27.76 R357.2
  BOTTOM w0.102: J27.47 41.86,25 42.01,24.86 42.27,24.86 v1(42.49,25.08)
PCIE20_TXP: length 34.1
  TOP w0.102: J2.190 36.92,52.42 36.83,52.32 36.83,52.2 38.43,50.6 43.54,50.6 44.4,49.73 44.4,47.62 47.02,45.01 47.02,27.84 46.56,27.38 46.12,27.38 C213.1
PCIE20_TXP_: length 6.2
  TOP w0.102: v1(42.49,24.38) 42.72,24.61 43.01,24.61 43.26,24.86 43.26,26.01 42.39,26.88 42.39,27.41 42.49,27.51 42.68,27.51 R358.2
  BOTTOM w0.102: v1(42.49,24.38) 42.27,24.6 41.96,24.6 41.86,24.5 J27.49
PCIE20_WAKEN_3V3_L: length 2.6
  TOP w0.127: v1(49.5,23.06) 49.76,22.81 R349.2
  BOTTOM w0.127: v1(49.5,23.06) 49.01,23.06 48.82,23.25 J27.54
PCIE20_WAKEN_M2_3V3_L: length 60.4
  TOP w0.127: J2.4 85.42,52.4 84.79,51.77 84.79,51.26 83.2,49.67 83.2,42.43 84.02,41.61 84.02,37.41 84.53,36.91 84.53,36.53 84.15,36.14 84.15,35.69 84.91,34.92 v1(85.04,34.92) ; R349.1 v1(51.56,22.81)
  BOTTOM w0.127: v1(85.04,34.92) 84.81,34.92 84.38,35.36 78.79,35.36 73.66,30.23 73.66,29.34 68.91,24.59 68.9,24.59 55.06,24.59 55.06,24.59 54.48,24.59 54.06,24.59 54.05,24.59 52.27,22.81 v1(51.56,22.81)
PHY0_CLKOUT125: length 4.9
  TOP w0.127: U19.35 41.22,40.01 41.41,39.83 R216.2
PHY0_G_LED-: length 22.4
  TOP w0.127: R213.1 34.37,73.94 33.6,74.7 32.15,74.7 26.54,80.31 26.54,84.71 27.91,86.08 J22.12
PHY0_LED0/CFG_EXT: length 3.4
  TOP w0.203: R226.1 R225.2 38.48,38.13 37.8,38.81 U19.32
PHY0_LED1/CFG_LDO0: length 180.2
  TOP w0.127: v1(14.68,10.74) 17.65,10.74 18.16,11.25 21.94,11.25 24.48,13.79 26.7,13.79 28.09,15.19 29.92,15.19 31.57,16.84 31.57,17.98 31.57,18.19 33.17,19.79 33.96,19.79 34.38,19.79 35.25,20.65 36.22,20.65 37.72,22.15 39.37,22.15 v1(39.9,22.68) ; v1(33.86,75.13) 32.08,75.13 27.05,80.16 27.05,83.59 29.59,86.13 J22.11 ; v1(42.49,36.09) 41.92,36.67 R233.2 C133.2 41.92,37.84 41.15,38.61 39.14,38.61 38.54,39.21 U19.33
  BOTTOM w0.127: v1(42.49,36.09) 43.13,35.46 43.13,34.37 43.97,33.53 43.97,28.19 44.78,27.38 44.78,23.67 43.01,21.89 41.27,21.89 41,22.16 39.96,22.16 39.83,22.3 39.83,22.61 v1(39.9,22.68) ; v1(14.68,10.74) 12.65,10.74 9.86,13.54 3.63,13.54 2.87,14.3 2.87,20.4 3.25,20.78 3.25,68.99 4.6,70.33 10.67,70.33 12.04,68.96 16.97,68.96 18.29,70.28 33.63,70.28 34.32,70.97 34.32,73.28 33.86,73.74 v1(33.86,75.13)
PHY0_LED2/CFG_LDO1: length 193
  TOP w0.127: v1(14.17,10.24) 14.94,10.24 15.15,10.45 17.74,10.45 18.29,11 22.05,11 24.59,13.54 26.82,13.54 28.22,14.94 30.05,14.94 31.83,16.71 31.83,18.08 33.27,19.53 33.86,19.53 33.86,19.53 34.49,19.53 35.28,20.32 36.3,20.32 37.87,21.89 40.03,21.89 40.23,21.7 v1(40.28,21.7) ; R230.1 44.36,37.61 v1(43.96,38) 43.66,38.3 42.5,38.3 C132.2 41.61,39.19 41.1,39.19 40.89,38.99 39.78,38.99 39.25,39.52 R229.2 39.16,39.61 U19.34 ; v1(33.27,73.86) 32.27,73.86 21.66,84.48 17.35,84.48 16.13,85.7 16.13,86.59 16.74,87.2 18.67,87.2 J22.13
  BOTTOM w0.127: v1(43.96,38) 44.02,37.95 44.02,37.41 43.38,36.78 43.38,34.49 44.22,33.66 44.22,28.32 44.65,27.89 44.65,27.87 45.03,27.49 45.03,23.52 43.05,21.54 41,21.54 40.84,21.7 v1(40.28,21.7) ; v1(14.17,10.24) 12.78,10.24 9.73,13.28 3.51,13.28 2.62,14.17 2.62,20.52 3,20.9 3,69.11 4.47,70.59 10.77,70.59 12.14,69.22 16.87,69.22 18.21,70.56 33.53,70.56 34.06,71.09 34.06,72.77 33.27,73.56 v1(33.27,73.86)
PHY0_MDI0+: length 3.5
  TOP w0.102: R223.1 38.27,44.11 38.27,43.85 37.52,43.1 37.03,43.1 36.98,43.15 36.58,43.15 36.45,43.02 36.45,42.95 36.55,42.85 U19.1
PHY0_MDI0-: length 3.3
  TOP w0.102: U19.2 36.15,42.88 36.25,42.98 36.25,43.11 36.5,43.36 37.41,43.36 38.01,43.96 38.01,44.11 R222.1
PHY0_MDI1+: length 2.2
  TOP w0.102: U19.4 35.35,42.86 35.27,42.93 35.27,43.27 35.51,43.51 35.51,44.15 R221.1
PHY0_MDI1-: length 2.2
  TOP w0.102: U19.5 34.95,42.87 35.02,42.94 35.02,43.38 35.26,43.62 35.26,44.08 R220.1
PHY0_MDI2+: length 2.6
  TOP w0.102: R425.1 33.66,44.13 33.66,44.07 33.76,43.97 34.15,43.97 34.47,43.64 34.47,42.94 34.55,42.87 U19.6
PHY0_MDI2-: length 2.6
  TOP w0.102: R424.1 33.41,44.15 33.41,43.96 33.66,43.71 34.04,43.71 34.22,43.54 34.22,42.96 34.15,42.88 U19.7
PHY0_MDI3+: length 3.9
  TOP w0.102: U19.9 33.35,42.88 33.27,42.95 33.27,43.13 33.02,43.38 32.05,43.38 31.55,43.89 31.09,43.89 30.96,44.02 30.96,44.1 R215.1
PHY0_MDI3-: length 3.9
  TOP w0.102: R214.1 30.71,44.05 30.71,43.92 30.99,43.64 31.44,43.64 31.95,43.13 32.92,43.13 33.02,43.03 33.02,42.93 32.95,42.85 U19.10
PHY0_RSTN: length 5.7
  TOP w0.127: U19.12 31.82,41.61 31.55,41.88 29.7,41.88 29.14,42.44 28.19,42.44 C143.2 R248.2
PHY0_RXCLK/PHYAD1: length 8.3
  TOP w0.127: R238.1 33.63,31.41 33.63,32.68 R256.1 34.52,33.57 34.52,34.98 34.04,35.45 R237.2 34.04,35.97 35.35,37.28 U19.27
PHY0_RXD0/RXDLY: length 9.1
  TOP w0.127: R240.1 32.59,31.39 32.59,32.66 R252.1 31.57,33.67 31.57,34.94 R239.2 32.65,36.02 33.1,36.02 34.55,37.47 U19.25
PHY0_RXD1/TXDLY: length 9.7
  TOP w0.127: R243.1 31.57,31.39 31.57,32.66 R253.1 30.61,33.62 30.61,34.97 R242.2 32.04,36.4 33.1,36.4 34.15,37.45 U19.24
PHY0_RXD2/PLLOFF: length 10.3
  TOP w0.127: R246.1 30.56,31.39 30.56,32.66 R254.1 29.54,33.67 29.54,34.87 R245.2 31.33,36.65 32.97,36.65 33.75,37.43 U19.23
PHY0_RXD3/PHYAD0: length 10.4
  TOP w0.127: U19.22 33.35,37.41 32.84,36.91 30.76,36.91 29.16,35.31 29.16,33.29 R255.1 29.54,32.66 29.54,31.36 R236.1
PHY0_RXDV/PHYAD2: length 5.9
  TOP w0.127: R257.1 32.59,33.67 32.59,34.94 R235.2 33.1,35.64 34.95,37.49 U19.26
PHY0_XTALIN: length 9.6
  TOP w0.203: XT3.3 44.23,42.37 42.62,42.37 42.06,41.8 C130.2 41.55,41.8 41.35,41.6 41.35,41.1 40.66,40.41 U19.36
PHY0_XTALOUT: length 8.5
  TOP w0.203: XT3.1 43.37,43.25 42.88,42.75 42.24,42.75 42.06,42.93 C129.2 41.99,42.62 41.76,42.4 41.63,42.4 40.97,41.73 40.97,41.22 40.55,40.81 U19.37
PHY0_Y_LED+: length 71.4
  TOP w0.127: v1(43.51,49.48) 43.51,45.97 42.32,44.78 R211.1 ; J22.14 18.42,84.91 21.58,84.91 32.12,74.37 33.55,74.37 34.11,73.81 34.11,69.24 v1(33.88,69.01) ; v1(48.97,48.73) 48.92,48.67 48.66,48.67 47.96,49.38 47.96,51.89 48.26,52.2 48.26,54.25 47.96,54.56 41.17,54.56 v1(39.76,55.97)
  BOTTOM w0.127: v1(39.76,55.97) 39.07,56.67 39.07,66.22 36.63,68.66 34.01,68.66 33.88,68.78 v1(33.88,69.01) ; v1(48.97,48.73) 48.7,48.46 44.53,48.46 v1(43.51,49.48)
PHY1_CLKOUT125: length 3.2
  TOP w0.127: U20.35 63.9,39.88 64.74,39.04 64.98,39.04 R270.2
PHY1_G_LED-: length 12.6
  TOP w0.127: J23.12 46.74,86.13 50.88,81.99 50.88,80.39 52.65,78.61 52.65,76.48 52.5,76.33 R268.1
PHY1_LED0/CFG_EXT: length 7
  TOP w0.127: R274.1 66.5,35.08 65.67,35.08 R273.2 65.16,35.61 63.32,37.45 63.32,38.18 62.82,38.68 U20.32
PHY1_LED1/CFG_LDO0: length 74.3
  TOP w0.127: U20.33 62.8,39.08 63.58,38.3 63.58,37.8 64.8,36.58 R281.2 65.16,36.85 64.08,37.92 64.08,38.48 v1(63.5,39.07) ; J23.11 49.25,84.26 51.26,82.25 51.26,80.37 52.91,78.72 52.91,77.01 53.52,76.4 C157.2 53.68,76.09 55.02,74.75 55.02,72.54 58.24,69.32 58.24,67.26 57.48,66.5 57.48,63.32 57.99,62.81 60.68,62.81 v1(60.93,63.07) ; v1(69.67,54.56) v1(62.31,54.56)
  BOTTOM w0.127: v1(62.31,54.56) 62.31,55.96 60.93,57.33 v1(60.93,63.07) ; v1(63.5,39.07) 64.01,38.56 65.38,38.56 66.62,39.8 66.62,40.97 69.42,43.76 69.42,54.31 v1(69.67,54.56)
PHY1_LED2/CFG_LDO1: length 97
  TOP w0.127: C156.2 36.27,68.37 v1(36.27,69.16) 36.27,70.69 35.64,71.32 35.64,75.51 39.45,79.32 39.45,83.13 38.54,84.04 J23.13 ; v1(54.49,74.27) 54.49,72.69 57.99,69.19 57.99,67.39 57.23,66.62 57.23,63.2 57.86,62.56 61.16,62.56 61.42,62.81 v1(61.93,62.81) ; v1(62.84,48.51) 62.97,48.51 65.56,45.92 67.01,45.92 70,42.93 70,38.68 68.53,37.21 67.67,37.21 R278.1 66.61,37.31 65.71,37.31 65.23,37.8 R277.2 64.47,38.49 64.47,38.81 63.74,39.53 63.15,39.53 63.1,39.48 U20.34
  BOTTOM w0.127: v1(62.84,48.51) 63.04,48.72 63.04,55.98 61.8,57.23 61.8,62.69 v1(61.93,62.81) ; v1(36.27,69.16) 37.54,70.43 50.16,70.43 50.62,70.43 53.62,73.43 54,73.43 54.52,73.95 54.52,74.13 54.49,74.16 v1(54.49,74.27)
PHY1_MDI0+: length 3.7
  TOP w0.102: R266.1 63.78,44.1 63.78,43.92 62.84,42.98 61.81,42.98 61.72,42.89 61.72,42.8 61.82,42.7 U20.1
PHY1_MDI0-: length 3.6
  TOP w0.102: U20.2 61.42,42.7 61.52,42.8 61.52,42.98 61.72,43.18 62.68,43.18 63.53,44.02 63.53,44.13 R265.1
PHY1_MDI1+: length 2.4
  TOP w0.102: R264.1 61.04,44.08 61.04,43.76 60.55,43.27 60.55,42.86 60.62,42.78 U20.4
PHY1_MDI1-: length 2.4
  TOP w0.102: U20.5 60.22,42.8 60.29,42.87 60.29,43.38 60.78,43.87 60.78,44.08 R263.1
PHY1_MDI2+: length 2.4
  TOP w0.102: U20.6 59.82,42.98 59.75,43.06 59.75,43.38 59.21,43.92 59.21,44.15 R262.1
PHY1_MDI2-: length 2.4
  TOP w0.102: U20.7 59.42,42.98 59.49,43.06 59.49,43.28 58.95,43.81 58.95,44.13 R261.1
PHY1_MDI3+: length 3.8
  TOP w0.102: U20.9 58.62,42.73 58.55,42.8 58.55,42.98 58.27,43.26 57.88,43.26 57.76,43.13 57.2,43.13 56.62,43.72 56.62,44.15 R260.1
PHY1_MDI3-: length 3.8
  TOP w0.102: R259.1 56.36,44.15 56.36,43.61 57.1,42.88 57.86,42.88 57.99,43 58.16,43 58.29,42.87 58.29,42.8 58.22,42.73 U20.10
PHY1_RSTN: length 3.3
  TOP w0.127: R296.2 C167.2 55.96,42.37 56.34,41.99 56.59,41.99 57.1,41.48 U20.12
PHY1_RXCLK/PHYAD1: length 6.4
  TOP w0.127: R304.1 R284.2 59.82,35.07 ; 59.82,35.07 59.82,36.58 60.62,37.38 U20.27 ; 59.82,35.07 60.27,34.61 60.27,33.48 60.08,33.28 R285.1
PHY1_RXD0/RXDLY: length 9.4
  TOP w0.127: R287.2 57.82,31.11 57.35,31.57 57.35,32.4 R288.1 57.35,33.42 57.35,34.56 R300.1 57.31,35.53 57.51,35.53 57.51,35.54 58.01,35.54 59.82,37.34 U20.25
PHY1_RXD1/TXDLY: length 9.9
  TOP w0.127: R291.1 56.34,32.4 R290.2 56.34,33.42 56.34,34.56 R301.1 56.57,35.81 57.91,35.81 59.42,37.32 U20.24
PHY1_RXD2/PLLOFF: length 10.5
  TOP w0.127: U20.23 59.02,37.3 57.81,36.09 56.41,36.09 55.96,35.64 55.38,35.64 R302.1 55.32,34.56 55.32,33.42 R293.2 55.32,32.4 R294.1
PHY1_RXD3/PHYAD0: length 8.7
  TOP w0.127: R283.1 53.29,33.42 53.29,34.56 R303.1 54.62,35.89 55.83,35.89 56.29,36.35 57.58,36.35 58.62,37.39 U20.22
PHY1_RXDV/PHYAD2: length 6.3
  TOP w0.127: U20.26 60.22,37.36 57.93,35.07 R286.2 58.37,34.56 58.37,33.42 R305.1
PHY1_XTALIN: length 7.4
  TOP w0.203: U20.36 65.36,40.28 C153.2 66.11,41.03 66.31,41.03 66.62,41.35 67.59,41.35 XT4.3
PHY1_XTALOUT: length 5.4
  TOP w0.203: XT4.1 66.27,41.83 65.9,41.83 C154.2 64.75,40.68 U20.37
PHY1_Y_LED+: length 22
  TOP w0.127: R267.1 35.76,67.95 35.76,70.69 35.33,71.12 35.33,75.59 39.19,79.45 39.19,82.93 J23.14
PWM3_IR: length 121.8
  TOP w0.127: J2.124 55.42,51.99 52.43,49 52.43,45.95 52.32,45.84 52.32,44.28 52.73,43.87 52.88,43.87 52.89,43.86 v1(52.96,43.86) ; R311.3 127.13,28.58 127,28.71 127,28.86 125.15,30.71 125.06,30.71 124.82,30.94 124.49,30.94 123.98,31.45 120.73,31.45 119.51,32.66 119.51,35.69 120.35,36.53 120.35,41.48 v1(119.46,42.37)
  BOTTOM w0.127: v1(52.96,43.86) 52.37,43.86 51.77,43.26 51.77,31.19 53.04,29.92 56.34,29.92 57.1,29.16 66.88,29.16 73.74,36.02 73.74,37.03 74.5,37.8 75.51,37.8 77.67,39.95 94.8,39.95 94.95,39.81 97.59,37.16 99.52,37.16 99.9,37.54 105.36,37.54 106.12,38.3 109.04,38.3 113.36,42.62 119.2,42.62 v1(119.46,42.37)
PWM3_IR_: length 2.9
  TOP w0.127: R311.6 128.91,28.58 128.98,28.66 130.26,28.66 J24.23
PWM13_M1: length 5.1
  TOP w0.127: J2.144 50.45,53.23 50.45,52.45 51.03,51.87 51.03,50.11 50.22,49.3 R110.1
PWRON: length 2.9
  TOP w0.127: J24.25 129.95,26.87 129.82,26.75 128.83,26.75 128.73,26.85 R314.2
RESET: length 5.7
  TOP w0.127: J24.26 132.32,28.11 128.98,28.11 128.91,28.03 R311.5
RK809-CLK32K: length 149.4
  TOP w0.127: v1(23.35,56.1) 23.42,56.17 23.42,56.31 23.34,56.39 23.34,59.36 22.67,60.03 J2.247 ; R205.1 v1(97.49,19.63)
  BOTTOM w0.127: v1(23.35,56.1) 23.35,55.84 23.11,55.6 23.11,55.1 23.03,55.02 23.03,54.61 23.03,54.4 23.29,54.14 23.29,44.98 22.31,44.01 22.31,43.52 22.17,43.38 22.17,26.69 22.86,26 24.06,26 24.59,25.48 24.59,24.59 23.57,23.57 23.57,22.81 22.56,21.79 22.56,18.62 23.7,17.48 23.7,14.4 25.07,13.03 26.37,13.03 29.03,10.36 29.03,8.16 30.64,6.55 34.62,6.55 37.54,3.63 70.94,3.63 72.47,5.16 91.03,5.16 91.3,5.42 96.88,5.42 96.89,5.44 97.25,5.44 98.45,6.63 98.9,7.08 99.97,7.08 100.61,7.72 100.61,9.27 100.03,9.86 100.03,12.9 99.52,13.41 99.52,17.6 v1(97.49,19.63)
RK809_PWRON: length 212.1
  TOP w0.127: v1(78.33,81.03) 78.33,80.44 77.04,79.15 77.04,73.03 76.91,72.9 75.82,72.9 75.44,72.51 75.44,71.6 75.72,71.32 75.72,70.59 76.02,70.28 76.02,69.55 75.57,69.1 R412.1 75.47,68.43 C259.2 ; J2.251 21.67,60.53 21.5,60.35 18.8,60.35 18.52,60.63 18.52,66.4 v1(18.75,66.62) ; v1(129.69,27.3) 129.57,27.43 127.67,27.43 127.44,27.2 127.44,26.97 127.34,26.87 R314.1
  BOTTOM w0.127: v1(129.69,27.3) 129.69,27.74 129.87,27.91 129.87,37.67 130.38,38.18 131.52,38.18 132.41,39.07 132.41,58.88 129.9,61.39 129.9,68.78 133.5,72.39 133.5,76.45 131.39,78.56 126.24,78.56 125.63,77.95 125.09,77.95 124.16,78.89 124.16,79.68 122.73,81.1 119.96,81.1 118.57,79.71 114.91,79.71 114.15,80.47 92.66,80.47 90.37,82.75 82.5,82.75 80.04,80.29 78.33,80.29 ; 78.33,80.29 v1(78.33,81.03) ; 78.33,80.29 72.23,80.29 71.14,79.2 69.8,79.2 68.78,80.21 59.03,80.21 57.47,80.21 56.53,79.27 55.63,79.27 53.19,76.83 53.19,75.16 52.39,74.36 52.39,72.61 50.47,70.69 50.26,70.69 37.03,70.69 35.84,69.49 21.62,69.49 v1(18.75,66.62)
RK809_VDC: length 89.5
  TOP w0.127: v1(74.98,80.9) 75.8,80.08 75.8,76.57 R9.2 R7.1 ; J2.252 21.42,55.82 20.9,56.34 17.86,56.34 17.22,56.97 17.22,60.15 18.26,61.19 18.26,66.9 v1(18.75,67.39)
  BOTTOM w0.127: v1(18.75,67.39) 19.13,67.39 21.39,69.65 21.41,69.65 21.51,69.75 35.71,69.75 36.91,70.94 50.37,70.94 52.14,72.71 52.14,74.47 52.93,75.27 52.93,76.94 55.52,79.53 56.42,79.53 57.36,80.47 60.75,80.47 60.75,80.47 68.91,80.47 69.93,79.45 71.03,79.45 72.13,80.54 74.65,80.54 74.98,80.87 v1(74.98,80.9)
RSET0: length 2.5
  TOP w0.127: R241.2 38.68,42.37 37.93,41.61 U19.39
RSET1: length 5
  TOP w0.127: R289.2 65.3,43.87 65.3,43.51 63.91,42.11 63.65,42.11 63.02,41.48 U20.39
RTCIC_32KOUT: length 56.2
  TOP w0.127: R206.1 97.79,20.65 v1(97.49,20.96) ; v1(82.35,17.55) 82.17,17.55 78.31,21.41 78.31,22.3 75.21,25.4 75.21,31.52 75.87,32.18 75.87,33.2 76.02,33.35 76.02,35.1 77.42,36.5 U21.7
  BOTTOM w0.127: v1(97.49,20.96) 98.43,20.96 99.03,21.56 99.03,27.27 98.44,27.86 96.09,27.86 92.28,24.06 89.62,24.06 89.41,24.06 89.2,24.06 88.84,24.41 86.32,24.41 85.21,23.3 85.19,23.3 84.55,22.66 84.55,22.64 82.38,20.47 82.38,17.58 v1(82.35,17.55)
SARADC_VIN0_: length 3.1
  TOP w0.127: R312.8 129.71,25.64 131.01,24.33
SARADC_VIN0_KEY/RECOVERY: length 135.7
  TOP w0.127: v1(117.42,65.61) 117.07,65.96 117.07,67.23 116.89,67.41 116.89,71.86 117.39,72.35 117.39,73.57 117.68,73.86 120.85,73.86 121.18,73.53 122.81,73.53 123.14,73.86 123.14,75.51 122.22,76.43 121.84,76.43 v1(121.49,76.78) 121.29,76.98 C182.2 R330.1 ; J2.1 86.22,61.4 87.9,61.4 90.55,58.75 90.55,57.78 93.55,54.79 95.78,54.79 98.02,57.02 108.61,57.02 109.44,56.19 v1(109.44,55.8) ; v1(116.33,64.14) 115.57,64.14 115.27,63.83 114.25,63.83 111.12,60.71 111.12,57.45 111.89,56.69 v1(111.91,56.69) ; v1(129.77,26.14) 129.67,26.24 128.93,26.24 128.72,26.03 127.76,26.03 127.64,25.92 127.64,25.77 127.52,25.64 R312.1
  BOTTOM w0.127: v1(111.91,56.69) 111.79,56.69 110.89,55.8 v1(109.44,55.8) ; v1(121.49,76.78) 121.49,77.17 122,77.67 125.81,77.67 126.42,78.28 131.22,78.28 133.17,76.33 133.17,72.52 129.62,68.96 129.62,61.29 132.16,58.75 132.16,39.19 131.39,38.43 130.25,38.43 129.62,37.8 129.62,28.3 129.22,27.9 129.22,26.46 129.44,26.24 129.67,26.24 v1(129.77,26.14) ; v1(117.42,65.61) 117.42,64.52 117.04,64.14 v1(116.33,64.14)
SARADC_VIN2_: length 4
  TOP w0.127: J24.29 130.25,22.56 130.25,22.99 128.65,24.59 R312.6
SARADC_VIN2_HP_HOOK: length 72.1
  TOP w0.127: R312.3 126.69,24.59 126.41,24.87 126.41,28.11 126.24,28.29 126.24,28.55 124.84,29.94 124.74,29.94 124.51,30.18 123.39,30.18 122.63,30.94 120.47,30.94 119,32.41 119,35.94 119.84,36.78 119.84,40.84 118.44,42.24 118.44,43.28 111.2,50.52 111.2,54.25 109.91,55.55 109.91,56.16 108.79,57.28 97.89,57.28 95.66,55.04 93.68,55.04 90.81,57.91 90.81,58.88 87.12,62.56 85.98,62.56 85.67,62.25 J2.3
SARADC_VIN3_: length 6.4
  TOP w0.127: R312.7 128.73,25.09 130.63,23.19 132.41,23.19 133.55,24.33
SARADC_VIN4: length 74
  TOP w0.127: R312.4 126.95,24.04 126.53,23.62 122.96,23.62 119.96,26.62 119.96,31.06 118.75,32.28 118.75,36.07 119.58,36.91 119.58,40.72 110.82,49.48 v1(110.36,49.48) ; v1(84.6,59.88) 84.67,59.96 J2.7
  BOTTOM w0.127: v1(84.6,59.88) 85.67,58.81 85.67,52.65 90.12,48.21 94.72,48.21 94.93,48.21 95.77,47.37 97.99,47.37 98.73,48.11 98.94,48.11 102.16,48.11 103.96,49.91 109.93,49.91 v1(110.36,49.48)
SARADC_VIN4_: length 8
  TOP w0.127: J24.30 132.28,20.52 130.63,20.52 129.87,21.29 129.87,22.78 128.61,24.04 R312.5
SCL_CAM0: length 46.4
  TOP w0.127: J19.7 63.02,9.68 63.82,10.48 D102.9 D102.2 v1(63.82,13.41) 63.82,14.22 R152.2 ; R159.1 44.93,13.96 v1(44.93,14.45)
  BOTTOM w0.127: v1(44.93,14.45) 44.91,14.48 44.24,14.48 43.43,15.29 40.49,15.29 39.93,14.73 38.76,14.73 38.3,14.27 38.3,10.74 38.73,10.31 39.8,10.31 39.93,10.19 39.93,9.6 40.56,8.97 43.74,8.97 45.53,10.76 54.16,10.76 54.2,10.8 54.23,10.8 54.26,10.82 54.28,10.82 54.58,11.13 62.31,11.13 63.22,12.04 63.22,13 63.63,13.42 63.81,13.42 v1(63.82,13.41)
SCL_CAM1: length 8.8
  TOP w0.127: R162.1 44.25,15.54 Q17.2 44.24,14.74 44.45,14.53 44.45,13.55 R159.2 44.26,12.34 D103.2 D103.9 44.26,9.9 43.97,9.6 43.97,8.77 J20.7
SDA_CAM0: length 43.5
  TOP w0.127: J19.8 62.52,9.69 62.82,9.99 D102.7 D102.4 62.82,13.04 62.94,13.16 v1(62.94,13.54) R153.2 ; R160.1 43.97,14.43 43.66,14.73 43.43,14.73 v1(43.38,14.68)
  BOTTOM w0.127: v1(43.38,14.68) 43.33,14.73 42.16,14.73 41.86,15.04 40.74,15.04 40.18,14.48 39.01,14.48 38.58,14.05 38.58,10.95 38.96,10.57 40.03,10.57 40.31,10.29 40.31,9.6 40.67,9.25 43.64,9.25 45.4,11.01 54.06,11.01 54.09,11.05 54.13,11.05 54.46,11.38 62.18,11.38 62.94,12.14 v1(62.94,13.54)
SDA_CAM1: length 8.5
  TOP w0.127: J20.8 43.43,8.79 43.43,9.63 43.26,9.8 D103.7 D103.4 43.26,12.33 R160.2 R161.1 42.52,13.52 42.52,14.55 42.18,14.89 Q16.2
SDMMC0_CLK: length 2
  TOP w0.127: R21.1 32.92,51.38 J2.206
SDMMC0_CLK_: length 104.7
  TOP w0.127: v1(40.21,48.08) 39.98,48.31 37.36,48.31 35.31,50.37 33.81,50.37 C30.2 R21.2 ; v1(105.59,71.07) 105.59,71.3 106.01,71.72 D4.1 D4.10 106.01,73.88 106.2,74.07 J3.5
  BOTTOM w0.127: v1(105.59,71.07) 106.38,70.28 106.38,69.42 106.25,69.29 106.25,68.61 105.87,68.22 105.85,68.22 105.82,68.2 105.77,68.2 105.76,68.19 105.16,68.19 105.15,68.2 100.74,68.2 100.68,68.14 100.67,68.14 100.55,68.02 97.56,68.02 96.82,67.28 94.84,67.28 93.78,66.22 84.91,66.22 83.11,68.02 70.35,68.02 70.28,67.95 70.26,67.95 69.82,67.51 69.24,67.51 67.61,65.89 67.03,65.89 64.85,63.7 64.85,47.19 64.08,46.43 56.13,46.43 54.05,48.51 52.85,48.51 52.64,48.51 52.32,48.51 52,48.51 51.58,48.51 49.75,46.69 43.56,46.69 43.1,47.14 41.27,47.14 41.07,47.35 40.69,47.35 40.37,47.66 40.37,47.92 v1(40.21,48.08)
